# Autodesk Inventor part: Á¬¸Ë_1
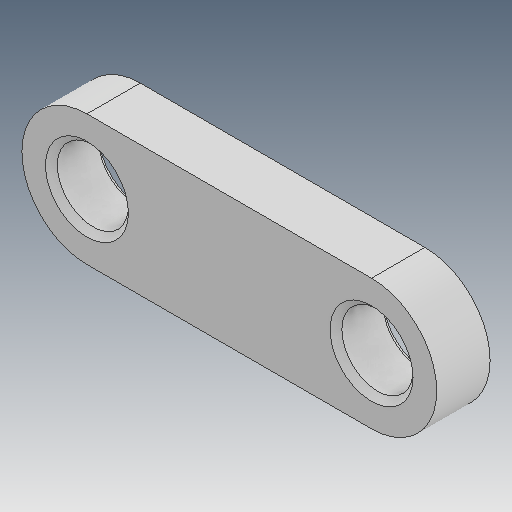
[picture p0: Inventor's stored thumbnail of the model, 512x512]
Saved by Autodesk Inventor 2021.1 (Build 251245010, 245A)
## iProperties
Created: 2019-04
Part Number: Á¬¸Ë_1
Material: Ogólny
Document SubType Name: Modeling
Designer: user
Density: 1 g/cm^3
Appearance: Domyślna
Author: user
Revision Number: ÈÎºÎ
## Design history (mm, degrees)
feature "ÊäÈë1"
node "Bryła1"
